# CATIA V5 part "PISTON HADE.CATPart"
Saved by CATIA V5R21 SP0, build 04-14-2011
Part number: Part1
Material "Gold Metal": density 7860 kg/m3, Young's modulus 2e+11 Pa, Poisson ratio 0.266
Bounding box of the stored display mesh (mm): x -45 to 45, y -45 to 45, z 0 to 60
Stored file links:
  G:\CATIA\PROJECT__01\PISTON HADE.CATPart
  C:\Program Files (x86)\Dassault Systemes\B21\intel_a\startup\materials\Catalog.CATMaterial
  C:\Program Files (x86)\Dassault Systemes\B21\intel_a\startup\materials\red_env_512x512.jpg
  C:\Program Files (x86)\Dassault Systemes\B21\intel_a\startup\materials\yellow_env_512x512.jpg
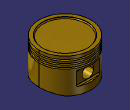
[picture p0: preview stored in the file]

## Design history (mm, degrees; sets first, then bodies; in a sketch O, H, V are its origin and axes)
Body1 (main body), material "Gold Metal"
  Sketch1 on xy-plane, origin (0, 0, 0), H (1, 0, 0), V (0, 1, 0)
    circle A1 centre (0, 0) radius 45
    radius A1 = 45
  Pad1: profile Sketch1, direction (0, 0, 1), length 60
  Sketch2 on yz-plane, origin (0, 0, 0), H (0, 1, 0), V (0, 0, 1)
    reference projected line E1 (45, 0) -> (45, 60) from face of Pad1 from Sketch1.A1
    point P2 (45, 60)
    line L1 (41, 55) -> (45, 55)
    line L2 (45, 55) -> (45, 52.5)
    line L3 (45, 52.5) -> (41, 52.5)
    line L4 (41, 52.5) -> (41, 55)
    axis line L5 (0, -7.9729) -> (0, 72.0558)
    point P9 (0, -7.9729)
    length L2 = 2.5
    length L3 = 4
    distance L1 P2 = 5
    horizontal: L1 H, L3 H
    vertical: L2 V, L4 V, L5 V
    coincidence: L2 E1, P9 V
  Groove1: profile Sketch2, axis Sketch2.L5, angle 360
  RectPattern1: of Groove1, direction 1 instances 3, spacing 6, along zx-plane reversed
  Sketch3 on end face of Pad1, origin (0, 0, 60), H (1, 0, 0), V (0, 1, 0)
    circle A1 centre (0, 0) radius 39
    radius A1 = 39
  Pocket1: profile Sketch3, direction (0, 0, -1), length 2
  Fillet1: radius 1.5, on edge [face of Pocket1 from Sketch3.A1 | end face of Pocket1]
  Sketch4 on yz-plane, origin (0, 0, 0), H (0, 1, 0), V (0, 0, 1)
    line L1 (0, 0) -> (0, 52)
    point P1 (0, 52)
    line L2 (0, 52) -> (13.3023, 52)
    point P2 (15, 52)
    line L3 (16.5514, 51.3105) -> (32.7491, 44.1115)
    point P3 (37.5, 42)
    line L4 (37.5, 36.801) -> (37.5, 0)
    point P4 (37.5, 0)
    line L5 (37.5, 0) -> (0, 0)
    reference projected line E1 (-45, 60) -> (45, 60) from edge [face of Pad1 from Sketch1.A1 | end face of Pad1]
    arc A1 centre (13.3023, 44) radius 8 from (13.3023, 52) to (16.5514, 51.3105) cw
    arc A2 centre (29.5, 36.801) radius 8 from (32.7491, 44.1115) to (37.5, 36.801) cw
    length L5 = 37.5
    distance L2 E1 = 8
    distance P2 P3 V = 10
    distance P1 P2 = 15
    radius A1 = 8
    radius A2 = 8
    vertical: L1 V, L4 V
    horizontal: L2 H, L5 H
    coincidence: P4 H, L2 P2, L3 P2, L3 P3, L4 P3
    tangency: A1 L2, A1 L3, A2 L3, A2 L4
  Groove2: profile Sketch4, axis axis of face of Pad1 from Sketch1.A1, angle 360
  Sketch5 on start face of Pad1, origin (0, 0, 0), H (1, 0, 0), V (0, -1, 0)
    projected circle E1 centre (0, 0) radius 37.5 from edge [face of Groove2 from Sketch4.L4 | start face of Pad1]
    projected arc E2 centre (0, 0) radius 37.5 from (20, 31.7214) to (-20, 31.7214) ccw from edge [face of Groove2 from Sketch4.L4 | start face of Pad1]
    projected arc E3 centre (0, 0) radius 37.5 from (-20, -31.7214) to (20, -31.7214) ccw from edge [face of Groove2 from Sketch4.L4 | start face of Pad1]
    point P1 (-20, 31.7214)
    line L1 (-20, 31.7214) -> (-15, 31.7214)
    line L2 (-12.5, 29.2214) -> (-12.5, 27.5)
    point P2 (-12.5, 25)
    axis line L3 (0, 0) -> (0, 37.5)
    point P3 (0, 37.5)
    line L4 (-10, 25) -> (0, 25)
    point P4 (0, 25)
    arc A1 centre (-15, 29.2214) radius 2.5 from (-15, 31.7214) to (-12.5, 29.2214) cw
    point P5 (-15, 31.7214)
    point P6 (-12.5, 29.2214)
    arc A2 centre (-10, 27.5) radius 2.5 from (-12.5, 27.5) to (-10, 25) ccw
    point P8 (-12.5, 27.5)
    point P9 (-10, 25)
    point P11 (20, 31.7214)
    point P12 (12.5, 25)
    point P13 (0, 37.5)
    point P14 (0, 25)
    point P15 (15, 31.7214)
    point P16 (12.5, 29.2214)
    point P18 (12.5, 27.5)
    point P19 (10, 25)
    line L5 (20, 31.7214) -> (15, 31.7214)
    line L6 (12.5, 29.2214) -> (12.5, 27.5)
    line L7 (10, 25) -> (0, 25)
    arc A3 centre (15, 29.2214) radius 2.5 from (15, 31.7214) to (12.5, 29.2214) ccw
    arc A4 centre (10, 27.5) radius 2.5 from (12.5, 27.5) to (10, 25) cw
    point P21 (-20, -31.7214)
    point P22 (-12.5, -25)
    point P23 (0, -37.5)
    point P24 (0, -25)
    point P25 (-15, -31.7214)
    point P26 (-12.5, -29.2214)
    point P28 (-12.5, -27.5)
    point P29 (-10, -25)
    point P31 (20, -31.7214)
    point P32 (12.5, -25)
    point P33 (0, -37.5)
    point P34 (0, -25)
    point P35 (15, -31.7214)
    point P36 (12.5, -29.2214)
    point P38 (12.5, -27.5)
    point P39 (10, -25)
    line L8 (-20, -31.7214) -> (-15, -31.7214)
    line L9 (-12.5, -29.2214) -> (-12.5, -27.5)
    line L10 (-10, -25) -> (0, -25)
    arc A5 centre (-15, -29.2214) radius 2.5 from (-15, -31.7214) to (-12.5, -29.2214) ccw
    arc A6 centre (-10, -27.5) radius 2.5 from (-12.5, -27.5) to (-10, -25) cw
    line L11 (20, -31.7214) -> (15, -31.7214)
    line L12 (12.5, -29.2214) -> (12.5, -27.5)
    line L13 (10, -25) -> (0, -25)
    arc A7 centre (15, -29.2214) radius 2.5 from (15, -31.7214) to (12.5, -29.2214) cw
    arc A8 centre (10, -27.5) radius 2.5 from (12.5, -27.5) to (10, -25) ccw
    distance P1 L3 = 20
    distance H L4 = 25
    radius A1 = 2.5
    distance P2 P4 = 12.5
    radius A2 = 2.5 {= Sketch5.radius(A1)}
    coincidence: P1 E1, P3 E1, P4 L3, L2 P2, L4 P2, P4 P14, P24 P34
    horizontal: L1 H, L4 H
    vertical: L2 V, L3 V
    tangency: A1 L1, A1 L2, A2 L2, A2 L4
    symmetry: P1 P11 L3, P2 P12 L3, P3 P13 L3, P4 P14 L3, P5 P15 L3, P6 P16 L3, P8 P18 L3, P9 P19 L3, L1 L5 L3, L2 L6 L3, L4 L7 L3, A1 A3 L3, A2 A4 L3, P1 P21 H, P2 P22 H, P3 P23 H, P4 P24 H, P5 P25 H, P6 P26 H, P8 P28 H, P9 P29 H, P11 P31 H, P12 P32 H, P13 P33 H, P14 P34 H, P15 P35 H, P16 P36 H, P18 P38 H, P19 P39 H, L1 L8 H, L2 L9 H, L4 L10 H, A1 A5 H, A2 A6 H, L5 L11 H, L6 L12 H, L7 L13 H, A3 A7 H, A4 A8 H
  Pad2: profile Sketch5, direction (0, 0, -1), up to the existing solid (limit type 2)
  Sketch6 on yz-plane, origin (0, 0, 0), H (0, 1, 0), V (0, 0, 1)
    line L1 (-32.5, 0) -> (32.5, 0)
    arc A1 centre (0, -120.7011) radius 125 from (-32.5, 0) to (32.5, 0) cw
    reference projected line E1 (45, 0) -> (45, 40.5) from face of Pad1 from Sketch1.A1
    reference projected line E2 (-45, 0) -> (-45, 40.5) from face of Pad1 from Sketch1.A1
    point P5 (45, 40.5)
    axis line L2 (45, 25) -> (-45, 25)
    point P8 (45, 25)
    point P9 (-45, 25)
    reference projected line E3 (-45, 0) -> (45, 0) from edge [start face of Pad1 | face of Pad1 from Sketch1.A1]
    point P10 (42.5, 25)
    line L3 (45, 37.5) -> (45, 12.5)
    line L4 (45, 12.5) -> (40, 12.5)
    line L5 (40, 12.5) -> (40, 37.5)
    line L6 (40, 37.5) -> (45, 37.5)
    point P11 (45, 37.5)
    point P12 (45, 12.5)
    point P13 (40, 12.5)
    point P14 (40, 37.5)
    point P15 (-45, 40.5)
    point P16 (-45, 25)
    point P17 (-42.5, 25)
    point P18 (-45, 37.5)
    point P19 (-45, 12.5)
    point P20 (-40, 12.5)
    point P21 (-40, 37.5)
    line L7 (-45, 37.5) -> (-45, 12.5)
    line L8 (-45, 12.5) -> (-40, 12.5)
    line L9 (-40, 12.5) -> (-40, 37.5)
    line L10 (-40, 37.5) -> (-45, 37.5)
    length L1 = 65
    radius A1 = 125
    distance L2 E3 = 25
    length L3 = 25
    distance L9 L5 = 80
    midpoint: L1 O
    horizontal: L1 H, L2 H, L4 H, L6 H
    coincidence: P8 E1, P9 E2, P10 L2, L3 E1
    vertical: L3 V, L5 V
    equidistance: L3 L5 P10, L4 L6 P10
    symmetry: P5 P15 V, P8 P16 V, P10 P17 V, P11 P18 V, P12 P19 V, P13 P20 V, P14 P21 V, L3 L7 V, L4 L8 V, L5 L9 V, L6 L10 V
  Pocket2: profile Sketch6, direction (-1, 0, 0), through (limit type 3), opposite side through (limit type 6)
  Sketch7 on face of Pocket2 from Sketch6.L5, origin (0, 40, 0), H (-1, 0, 0), V (0, 0, 1)
    axis line L1 (0, 37.5) -> (0, 12.5)
    point P1 (0, 37.5)
    point P2 (0, 12.5)
    reference projected point E1 (0, 37.5) from vertex [face of Pocket2 from Sketch6.L6 | face of Pad1 from Sketch1.A1]
    reference projected line E2 (20.6155, 12.5) -> (-20.6155, 12.5) from edge [face of Pocket2 from Sketch6.L4 | face of Pad1 from Sketch1.A1]
    circle A1 centre (0, 25) radius 10
    point P3 (0, 25)
    radius A1 = 10
    coincidence: P1 V, P1 E1, P2 E2
    vertical: L1 V
    midpoint: P3 L1
  Pocket3: profile Sketch7, direction (0, -1, 0), through (limit type 3)
  Fillet2: radius 2, on edge [face of Pocket2 from Sketch6.L4 | face of Pocket2 from Sketch6.L5]; edge [face of Pocket2 from Sketch6.L5 | face of Pocket2 from Sketch6.L6]; edge [face of Pocket2 from Sketch6.L10 | face of Pocket2 from Sketch6.L9]; edge [face of Pocket2 from Sketch6.L9 | face of Pocket2 from Sketch6.L8]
